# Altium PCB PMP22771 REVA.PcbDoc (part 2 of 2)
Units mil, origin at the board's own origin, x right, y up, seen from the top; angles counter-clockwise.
Board outline 3622.05 x 2204.72 mil, 4 copper layers (Top Layer, Signal Layer 1, Signal Layer 2, Bottom Layer), stack 35.634 mil thick; 91 components, 43 nets, 205 pads, 79 vias.
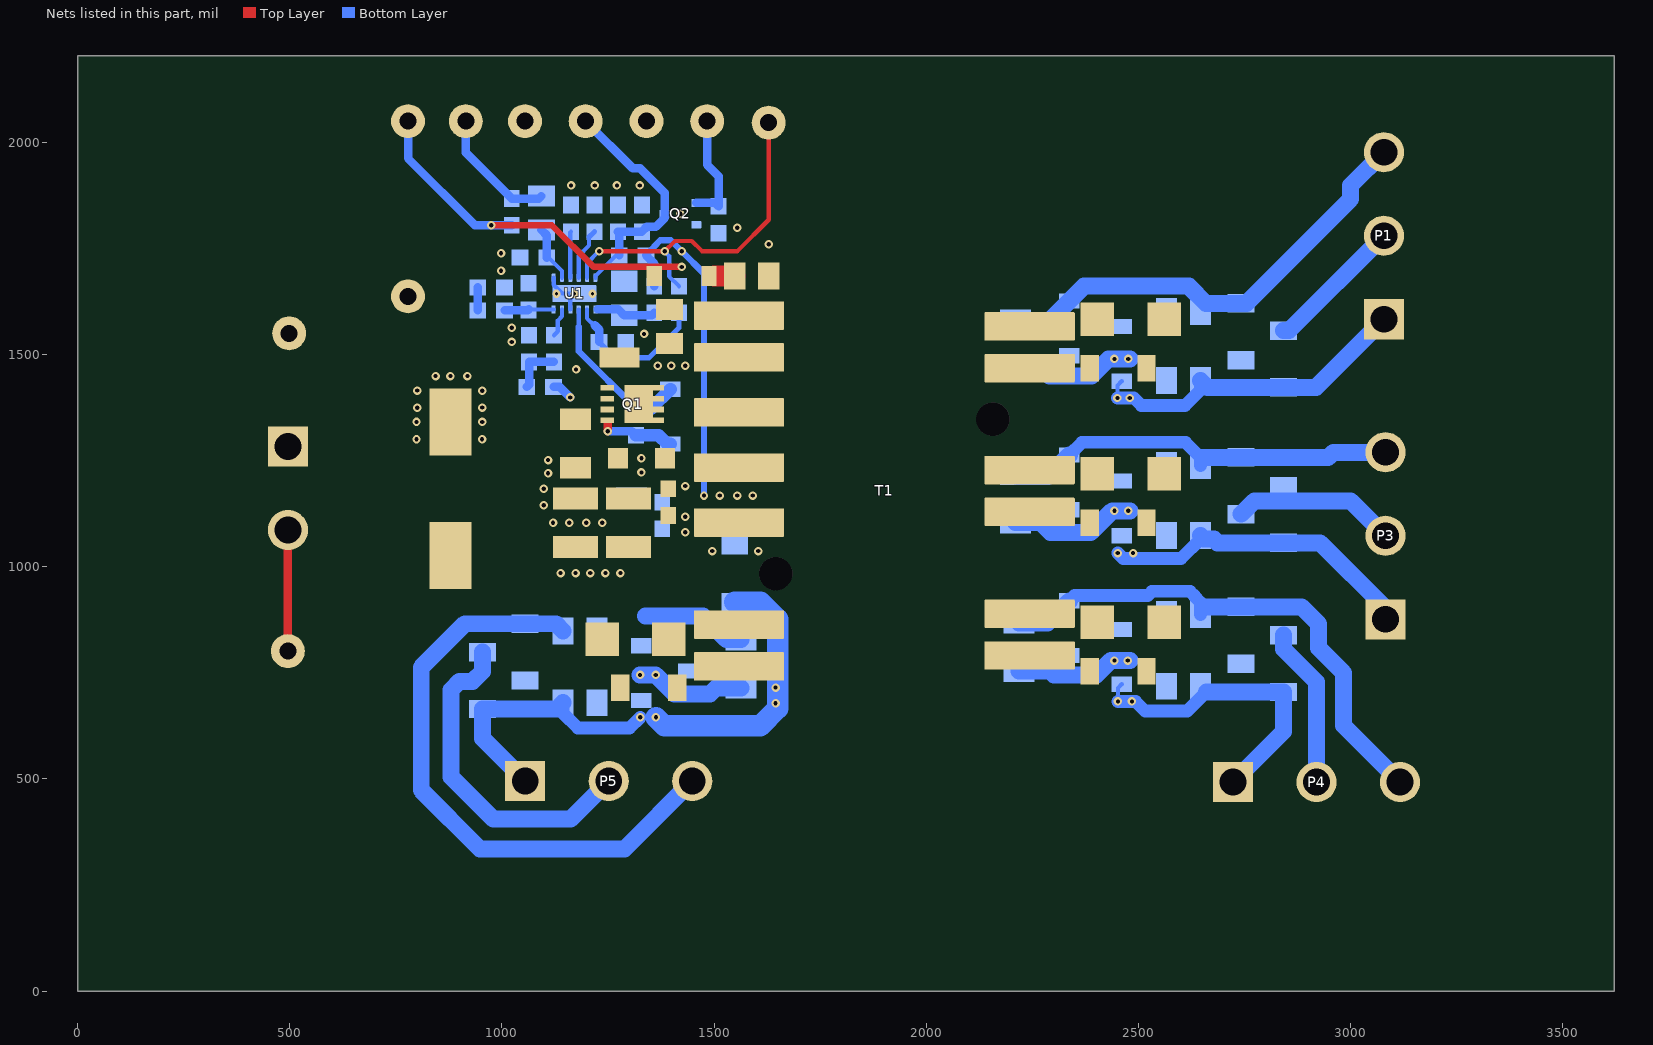
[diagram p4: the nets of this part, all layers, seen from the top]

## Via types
v1: diameter 20, hole 10, Top Layer to Bottom Layer, 76 vias
v2: diameter 19.68, hole 7.87, Top Layer to Bottom Layer, 3 vias

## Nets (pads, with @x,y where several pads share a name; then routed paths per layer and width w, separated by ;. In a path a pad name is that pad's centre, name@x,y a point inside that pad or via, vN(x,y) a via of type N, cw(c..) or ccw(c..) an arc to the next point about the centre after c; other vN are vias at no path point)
GND: C6.2 C7.2 C8.2 C9.2 C13.2 C16.2 C17.2 C21.2 C22.2 C23.2 C24.2 C25.2 C26.2 P2.1 Q2.2 R17.1 R21.1 R22.1 R26.1 R27.1 T1.2 TP2.1 TP8.1 TP9.1 TP10.1 U1.4 U1.7 U1.13@1171.25,1643.72 | length 115.9
  Bottom Layer w10: U1.7@1122.04,1681.12 1122.04,1664.47 1142.78,1643.72 v2(1171.25,1643.72) 1161.41,1633.88 U1.4@1161.41,1606.32
  other v1: 1495.85,1036.83 1604.33,1036.83 1120.69,1103.76 1158.82,1103.76 1198.82,1103.68 1236.81,1103.76 1098.82,1145.18 1098.82,1183.76 1432,1190.18 1108.82,1220.18 1108.82,1251.46 798.82,1300.18 953.3,1300.18 798.82,1341.24 953.82,1341.24 800.43,1374.7 953.82,1375.18 800.43,1415.18 953.82,1414.9 843.82,1449.26 878.82,1449.26 918.82,1449.26 1175,1465 1367.24,1473.72 1399.25,1473.72 1432.24,1473.72 1023.22,1529.88 1335.16,1548.6 1023.22,1562.95 998.22,1697.66 998.22,1738.72 1628.82,1760 1554.47,1798.72 1420.82,1831.67 1163.22,1898.72 1218.75,1898.72 1271.22,1898.72 1325.22,1898.72
  other v2: 1128.93,1643.72 1213.57,1643.72
GND2: C19.2 C20.2 C26.1 D14.2 P5.1 R20.1 T1.7 | length 1279.4
  Bottom Layer w30: R20.1@1144.29,679.57 1144.29,654.84 1179.13,620 1301.03,620 v1(1326.03,645)
  Bottom Layer w40: P5.1@1055,495 954.29,595.71 C20.2@954.29,664.86 1129.59,664.86 R20.1@1144.29,679.57
  Bottom Layer w50: v1(1362.96,645) 1382.96,625 1608.82,625 1650,666.18 1650,876.38 1609.62,916.75 C26.1@1548.82,916.75
  other v1: 1645,678.26 1645,715.19
NetC1_1: C1.1 D2.1 P1.3 R1.2 R2.2 | length 1084.9
  Bottom Layer w40: R1.2@2210.09,1580.81 2291.86,1580.81 D2.1@2337.24,1626.19 2372.15,1661.09 2618.91,1661.09 2659.35,1620.65 C1.1@2741.84,1620.65 2754.41,1620.65 2999.96,1866.2 2999.96,1898.11 P1.3@3078.7,1976.85
NetC1_2: C1.2 C3.1 D2.2 D3.1 P1.2 R2.1 R3.2 | length 329
  Bottom Layer w40: C3.1@2842.24,1556.51 2855.21,1556.51 P1.2@3078.7,1780
NetC2_1: C2.1 D1.1 R1.1 | length 293.5
  Bottom Layer w40: R1.1@2210.09,1466.63 2273.37,1466.63 2290,1450 2389.96,1450 2429.54,1489.58 v1(2443.5,1489.58) v1@2480.32,1489.58
  other v1: 2476,1489.58
NetC2_2: C2.2 C3.2 D3.2 P1.1 R3.1 T1.12 | length 789
  Bottom Layer w10: v1(2450.79,1397.64) 2450.79,1427.17 D3.2@2460.63,1437.01
  Bottom Layer w30: v1(2450.79,1397.64) v1(2480,1397.64) 2489.47,1397.64 2507.11,1380 2610,1380 2646.65,1416.65 R3.1@2646.65,1438.72
  Bottom Layer w40: R3.1@2646.65,1438.72 2662.71,1422.66 C3.2@2842.24,1422.66 2918.21,1422.66 P1.1@3078.7,1583.15
NetC4_1: C4.1 C6.1 C7.1 C8.1 C9.1 P2.2 R4.2 R8.2 R11.2 T1.4 T1.5 TP1.1 | length 1074.6
  Top Layer w20: TP1.1@495.71,801.08 495.71,1086.28 P2.2@495.94,1086.51
  Bottom Layer w15: R11.2@1339.71,1733.72 1358.62,1752.63 1358.62,1754.22 1373.49,1769.09 1375.08,1769.09 1375.71,1769.72 1397.86,1769.72 v1(1423.86,1743.72) 1476.38,1691.2 v1(1476.38,1167.73)
  Bottom Layer w20: R11.2@1339.71,1733.72 1359.25,1714.18 R8.2@1359.25,1661.24
  other v1: 1138.38,985.18 1173.82,985.18 1208.57,985.18 1243.97,985.18 1279.53,985.18 1432.24,1081.02 1432.24,1117.95 1513.31,1167.73 1554.47,1167.73 1591.4,1167.73
NetC4_2: C4.2 D4.1 R4.1
  other v1: 1328.82,1222.2 1328.82,1255.67
NetC5_1: C5.1 D6.1 P3.3 R5.2 R6.2 | length 941
  Bottom Layer w30: D6.1@2337.24,1263.19 2367.15,1293.09 2611.33,1293.09 2646.65,1257.78 R6.2@2646.65,1238.72
  Bottom Layer w40: R5.2@2210.39,1217.89 2215.63,1212.66 2286.71,1212.66 D6.1@2337.24,1263.19 ; R6.2@2652.03,1257.58 C5.1@2741.84,1257.58 2947.42,1257.58 2959.61,1269.77 P3.3@3082.52,1269.77
NetC5_2: C5.2 C11.1 D6.2 D7.1 P3.2 R6.1 R7.2 | length 387.6
  Bottom Layer w40: C5.2@2741.84,1123.72 2773.12,1155 3000.44,1155 P3.2@3082.52,1072.92
NetC10_1: C10.1 D5.1 R5.1 | length 300.4
  Bottom Layer w40: R5.1@2210.39,1103.72 2270.21,1103.72 2292.9,1081.02 2387.77,1081.02 2438.64,1131.89 v1(2443.5,1131.89) v1@2480.32,1131.89
  other v1: 2476,1131.89
NetC10_2: C10.2 C11.2 D7.2 P3.1 R7.1 T1.10 | length 761.5
  Bottom Layer w30: v1(2451.42,1032.35) 2464.43,1019.34 2600.72,1019.34 2646.24,1064.87 R7.1@2646.24,1073.72
  Bottom Layer w40: R7.1@2646.24,1073.72 2655.09,1064.87 2678.36,1064.87 2686.91,1056.32 C11.2@2842.24,1056.32 2928.68,1056.32 3082.52,902.48 P3.1@3082.52,876.07
  other v1: 2487.63,1032.35
NetC12_1: C12.1 D9.1 P4.3 R9.2 R10.2 | length 1240.4
  Bottom Layer w30: D9.1@2337.24,919.57 2349.77,932.1 2522.3,932.1 2532.18,941.98 2621.98,941.98 2632.24,931.71 2632.24,930.36 2646.65,915.95 R10.2@2646.65,887.6
  Bottom Layer w40: R9.2@2218.98,867.87 2285.54,867.87 D9.1@2337.24,919.57 ; R10.2@2651.71,905.65 C12.1@2741.84,905.65 2884.35,905.65 2925,865 2925,808.26 2983.15,750.11 2983.15,626.18 P4.3@3116.85,492.48
NetC12_2: C12.2 C15.1 D9.2 D10.1 P4.2 R10.1 R13.2 | length 378.4
  Bottom Layer w40: C15.1@2842.24,838.72 2842.24,806.3 2920,728.54 P4.2@2920,492.48
NetC13_1: C13.1 R8.1 U1.1 | length 146.8
  Bottom Layer w10: U1.1@1220.46,1606.32 1225.79,1606.36
  Bottom Layer w20: 1225.79,1606.36 1274.52,1606.32 C13.1@1288.22,1592.62 1353.62,1592.62 R8.1@1359.25,1598.25
NetC14_1: C14.1 D8.1 R9.1 | length 279.1
  Bottom Layer w40: R9.1@2218.98,753.69 2292.73,753.69 2301.68,744.74 2400.99,744.74 2434.97,778.72 v1(2443.5,778.72) v1@2480.32,778.72
  other v1: 2475,778.72
NetC14_2: C14.2 C15.2 D10.2 P4.1 R13.1 T1.8 | length 723.9
  Bottom Layer w10: v1(2451.97,682.48) 2451.97,714.28 D10.2@2460.63,722.93
  Bottom Layer w30: v1(2451.97,682.48) v1(2485,682.48) 2493.58,682.48 2516.06,660 2615.19,660 R13.1@2660.05,704.86
  Bottom Layer w40: R13.1@2660.05,704.86 C15.2@2842.24,704.86 2842.24,611.57 P4.1@2723.15,492.48
NetC16_1: C16.1 R28.2 U1.2 | length 357.4
  Bottom Layer w10: U1.2@1200.78,1606.32 1200.78,1585.41 1217.06,1569.13 1218.75,1569.13
  Bottom Layer w12: C16.1@1229.11,1529.88 1266.49,1492.5 1346.54,1492.5 1417.32,1563.28 R28.2@1417.32,1598.25
  Bottom Layer w20: 1218.75,1569.13 1229.46,1558.42 1229.11,1558.07 C16.1@1229.11,1529.88
NetC17_1: C17.1 R14.2 R15.1 | length 119.6
  Bottom Layer w20: R15.1@1058.77,1423.72 1064.12,1429.07 C17.1@1064.12,1482.65 R14.2@1122.57,1482.65
NetC18_1: C18.1 D13.1 P5.3 R16.2 R19.2 | length 1683.8
  Bottom Layer w40: R19.2@1144.16,848.72 1127.23,865.65 C18.1@1054.62,865.65 912.56,865.65 810,763.09 810,473.38 948.38,335 1288.7,335 P5.3@1448.7,495 ; 1338.23,883.37 D13.1@1439.24,883.37 1474.25,883.37 1528.88,828.74 R16.2@1563.7,828.74
NetC18_2: C18.2 C20.1 D13.2 D14.1 P5.2 R19.1 R20.2 | length 792.9
  Bottom Layer w40: C20.1@954.29,798.72 954.29,753.34 930.95,730 900.43,730 880,709.57 880,505 980,405 1161.85,405 P5.2@1251.85,495
NetC19_1: C19.1 D12.1 R16.1 | length 262.7
  Bottom Layer w40: v1(1325.57,745) v1(1362.5,745) 1407.34,700.16 1490,700.16 1504.41,714.57 R16.1@1563.7,714.57
NetC21_1: C21.1 Q2.3 R11.1 R21.2 TP4.1 U1.12 | length 577.1
  Bottom Layer w10: U1.12@1220.46,1681.12 1220.46,1685.05 1269.13,1733.72 R11.1@1276.72,1733.72
  Bottom Layer w20: TP4.1@1197.37,2050 1308.39,1938.98 1325.71,1938.98 1383.41,1881.28 Q2.3@1383.41,1831.67 1384,1831.09 1384,1822.06 1363.12,1801.18 1341.59,1801.18 C21.1@1330.13,1789.72 R21.2@1273.4,1789.72 1276.72,1786.4 R11.1@1276.72,1733.72
NetC22_1: C22.1 R23.2 U1.6 | length 116.6
  Bottom Layer w10: C22.1@1063.53,1606.32 U1.6@1122.04,1606.32
  Bottom Layer w20: R23.2@1006.37,1604.11 1061.33,1604.11 C22.1@1062.35,1605.14 C22.1@1063.53,1606.32
NetC23_1: C23.1 U1.9 | length 109.4
  Bottom Layer w10: U1.9@1161.41,1681.12 1161.41,1787.91 C23.1@1163.22,1789.72
NetC24_1: C24.1 R23.1 | length 54.2
  Bottom Layer w20: R23.1@943.38,1604.11 C24.1@943.38,1658.29
NetC25_1: C25.1 D15.1 R25.2 TP6.1 | length 886.9
  Top Layer w15: v1(975,1804.74) 1117.85,1804.74 1215.98,1706.62 v1(1423.86,1706.62)
  Bottom Layer w20: TP6.1@778.82,2050 778.82,1962.26 936.34,1804.74 v1(975,1804.74) R25.2@1023.22,1804.74
NetD1_2: D1.2 T1.13
NetD4_2: D4.2 Q1.5 Q1.6 Q1.7 Q1.8 Q1.9 T1.3 TP3.1
NetD5_2: D5.2 T1.11
NetD8_2: D8.2 T1.9
NetD11_1: D11.1 R12.1 U1.3 | length 389.4
  Bottom Layer w10: 1181.09,1565.94 U1.3@1181.09,1606.32
  Bottom Layer w15: 1181.09,1565.94 1181.09,1507.82 R12.1@1316.18,1372.73
  Bottom Layer w30: R12.1@1316.18,1372.73 1351.79,1372.73 D11.1@1397.24,1418.19
NetD11_2: D11.2 Q1.4 R12.2 | length 186.3
  Top Layer w10: Q1.4@1248.17,1344.9 1249.5,1343.56 1249.5,1336.92
  Top Layer w20: v1(1249.5,1319.29) 1249.5,1336.92
  Bottom Layer w20: v1(1249.5,1319.29) 1306.64,1319.29 R12.2@1316.18,1309.74
  Bottom Layer w30: R12.2@1316.18,1309.74 1369.5,1309.74 1389.99,1289.25 D11.2@1397.24,1289.25
NetD12_2: D12.2 T1.6
NetD15_2: D15.2 R18.1 | length 60.5
  Top Layer w30: D15.2@1488.28,1685.18 D15.2@1499.86,1685.18
  Top Layer w50: D15.2@1499.86,1685.18 R18.1@1548.82,1685.18
NetQ1_1: Q1.1 Q1.2 Q1.3 R15.2 R17.2 | length 49.5
  Bottom Layer w20: R15.2@1121.76,1423.72 1136.28,1423.72 v1(1161,1399)
NetQ2_1: Q2.1 R26.2 TP7.1 | length 268
  Bottom Layer w20: Q2.1@1458.22,1857.26 1502.79,1857.26 R26.2@1510.85,1849.21 1510.85,1920.17 1483.82,1947.2 TP7.1@1483.82,2050
NetR14_1: R14.1 U1.5 | length 68.6
  Bottom Layer w10: R14.1@1122.57,1545.65 1131.89,1554.97 1131.89,1580.32 1141.72,1590.15 U1.5@1141.72,1606.32
NetR18_2: R18.2 T1.1
NetR22_2: R22.2 U1.10 | length 124
  Bottom Layer w10: U1.10@1181.09,1681.12 1181.09,1732.89 1205.62,1757.42 R22.2@1205.62,1777.12
  Bottom Layer w12: R22.2@1205.62,1777.12 R22.2@1218.22,1789.72
NetR24_1: R24.1 R27.2 U1.8 | length 135.2
  Bottom Layer w10: R27.2@1105.9,1728.72 1110.23,1728.72 1141.72,1697.22 U1.8@1141.72,1681.12
  Bottom Layer w20: R24.1@1093.22,1793.72 1105.9,1781.04 R27.2@1105.9,1728.72
NetR24_2: R24.2 R25.1 TP5.1 | length 299.7
  Bottom Layer w20: TP5.1@915,2050 914.79,1976.16 R25.1@1023.22,1867.73 1087.23,1867.73 R24.2@1093.22,1873.72
NetR28_1: R28.1 TP11.1 U1.11 | length 849.4
  Top Layer w10: v1(1229.27,1743.71) v1(1384,1743.71) 1407.82,1767.53 1447.56,1767.53 1471.38,1743.71 1554.94,1743.71 1628.82,1817.59 TP11.1@1628.82,2046.46
  Bottom Layer w10: U1.11@1200.78,1681.12 1200.78,1715.22 v1(1229.27,1743.71) ; v1(1384,1743.71) 1384,1742.36 1394.24,1732.12 1394.24,1684.32 R28.1@1417.32,1661.24
pads on no net: T1. U1.13@1144.28,1643.72 U1.13@1198.22,1643.72

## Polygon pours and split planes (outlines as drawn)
GND on Top Layer "TOP_LAYER_GND_P092" (solid, remove dead copper, pour order 92): 1670,2204.72 1675,2199.72 1675,1030 0,1030 0,2204.72
GND on Top Layer "TOP_LAYER_GND_P090" (solid, remove dead copper, pour order 90): 1660,2210
GND2 on Top Layer "TOP_LAYER_GND2_P088" (solid, remove dead copper, pour order 88): 1662.82,797.24 1663.39,796.67 1663.39,679.57 1650,666.18 1420.28,666.18 1384.09,630 1325,630 1315,640 1315,663.26 1448.99,797.24 1465,797.24
NetC2_2 on Top Layer "TOP_LAYER_NETC2_2_P070" (solid, remove dead copper, pour order 70): 2145.67,1501.34 2407.54,1501.34 2416.81,1492.07 2416.81,1481.92 2497.99,1400.74 2497.99,1390.45 2490.82,1383.29 2366.71,1383.29 2312.99,1437.01 2147.86,1437.01 2145.67,1434.82
NetC14_2 on Top Layer "TOP_LAYER_NETC14_2_P068" (solid, remove dead copper, pour order 68): 2145.67,824.57 2349.05,824.57 2366.52,807.1 2397.7,807.1 2418.49,786.32 2418.49,765.08 2497.99,685.57 2497.99,676.15 2481.41,659.57 2397.16,659.57 2298.86,757.87 2145.67,757.87
NetC10_2 on Top Layer "TOP_LAYER_NETC10_2_P066" (solid, remove dead copper, pour order 66): 2145.67,1162.47 2402.51,1162.47 2419.8,1145.18 2419.8,1116.2 2497.99,1038.01 2497.99,1024.14 2487.63,1013.78 2396.49,1013.78 2312.99,1097.28 2145.67,1097.28
NetC19_1 on Top Layer "TOP_LAYER_NETC19_1_P048" (solid, remove dead copper, pour order 48): 1200.79,868.72 1329.05,868.72 1338.55,859.22 1338.55,805.17 1372.53,771.19 1372.53,739.86 1312.76,680.1 1249.33,680.1 1200.79,728.64
NetD12_2 on Top Layer "TOP_LAYER_NETD12_2_P042" (solid, remove dead copper, pour order 42): 1663.39,898.46 1408.04,898.46 1378.29,868.72 1353.84,868.72 1353.84,790.99 1419.5,790.77 1460.03,831.3 1662.82,831.3
NetC14_1 on Top Layer "TOP_LAYER_NETC14_1_P040" (solid, remove dead copper, pour order 40): 2598.43,907.62 2470.26,907.62 2457.24,894.6 2457.24,825.6 2433.33,801.68 2433.33,772.78 2438.39,767.72 2486.21,719.9 2544.92,719.9 2598.43,773.4
NetD8_2 on Top Layer "TOP_LAYER_NETD8_2_P036" (solid, remove dead copper, pour order 36): 2440.2,831.21 2440.2,914.03 2429.6,924.62 2153.54,924.62 2145.67,916.75 2145.67,856.3 2342.48,856.3 2366.71,832.07
NetC2_1 on Top Layer "TOP_LAYER_NETC2_1_P032" (solid, remove dead copper, pour order 32): 2598.43,1621.72 2472.6,1621.72 2457.24,1606.36 2457.24,1531.87 2433.08,1507.71 2433.08,1484.24 2480.32,1437.01 2537.97,1437.01 2598.43,1497.46
NetD1_2 on Top Layer "TOP_LAYER_NETD1_2_P028" (solid, remove dead copper, pour order 28): 2145.67,1598.25 2336.39,1598.25 2362.16,1624.02 2440.94,1624.02 2440.94,1543.4 2432.97,1535.43 2145.67,1535.43
NetC10_1 on Top Layer "TOP_LAYER_NETC10_1_P026" (solid, remove dead copper, pour order 26): 2598.43,1255.67 2473.65,1255.67 2458.14,1240.16 2458.14,1168.63 2451.97,1162.47 2433.78,1144.27 2433.78,1124.9 2456.31,1102.36 2488.86,1069.82 2536.36,1069.82 2598.43,1131.89
NetD5_2 on Top Layer "TOP_LAYER_NETD5_2_P022" (solid, remove dead copper, pour order 22): 2145.67,1261.14 2147.27,1259.55 2440.94,1259.55 2440.94,1180.49 2361.25,1180.49 2345.24,1196.49 2145.67,1196.49
NetC25_1 on Top Layer "TOP_LAYER_NETC25_1_P020" (solid, remove dead copper, pour order 20): 1427.17,1583.48 1427.17,1643.08 1439.24,1655.15 1439.24,1706.44 1430.66,1715.02 1354.93,1715.02 1342.67,1702.76 1342.67,1602.8 1364.66,1580.81 1427.17,1580.81
NetR18_2 on Top Layer "TOP_LAYER_NETR18_2_P016" (solid, remove dead copper, pour order 16): 1663.39,1561.72 1662.82,1562.29 1662.82,1712.6 1656.97,1718.44 1604.33,1718.44 1604.33,1656.63 1574.8,1627.1 1574.8,1624.02 1525.04,1624.02 1510.85,1609.82 1510.85,1576.92 1524.82,1562.95
NetQ1_1 on Top Layer "TOP_LAYER_NETQ1_1_P008" (solid, remove dead copper, pour order 8): 1269.68,1363.6 1269.68,1423.99 1257.06,1436.61 1166.69,1436.61 1138.38,1408.3 1138.38,1318.9 1209.94,1318.9 1210.63,1319.59 1209.23,1320.99 1209.23,1347.3 1225.53,1363.6
NetC4_2 on Top Layer "TOP_LAYER_NETC4_2_P004" (solid, remove dead copper, pour order 4): 1248.22,1279.86 1248.22,1221.85 1249,1221.85 1260.22,1210.63 1334.05,1210.63 1339.71,1216.3 1339.71,1261.14 1329.31,1271.55 1307.88,1271.55 1299.21,1280.22
NetD4_2 on Top Layer "TOP_LAYER_NETD4_2_P006" (solid, remove dead copper, pour order 6): 1663.39,1300.18 1663.39,1427.17 1427.17,1427.17 1407.48,1446.85 1356.74,1446.85 1329.87,1473.72 1330.13,1511.81 1326.19,1515.75 1229.27,1515.75 1229.27,1446.85 1269.69,1446.85 1279.53,1437.01 1279.13,1436.61 1279.13,1312.79 1361.61,1230.32 1407.82,1230.32 1407.82,1254.62 1453.37,1300.18
NetC4_1 on Top Layer "TOP_LAYER_NETC4_1_P002" (solid, remove dead copper, pour order 2): 442.91,1141.73 423.23,1122.05 423.23,968.4 442.91,948.72 1010.2,948.72 1035.89,974.41 1287.78,974.41 1328.74,1015.37 1348.59,1015.37 1403.04,1069.82 1663.39,1069.82 1663.39,1267.26 1453.31,1267.26 1453.7,1266.87 1453.7,1185.15 1389.04,1120.49 1322.4,1120.49 1281.91,1080 1110.86,1080 1049.13,1141.73
GND on Bottom Layer "BOTTOM_LAYER_GND_P094" (solid, remove dead copper, pour order 94): 1675,2204.72 1675,1030 0,1030 0,2204.72
NetC18_1 on Bottom Layer "BOTTOM_LAYER_NETC18_1_P086" (solid, remove dead copper, pour order 86): 1150.45,860 1181.81,891.36 1302.08,891.36 1327.72,865.72 1358.67,865.72 1358.67,883.39 1322.07,920 1160.29,920 1120,879.71 1120,860
NetC18_2 on Bottom Layer "BOTTOM_LAYER_NETC18_2_P082" (solid, remove dead copper, pour order 82): 1415,738.9 1465,738.9 1465,839.11 1424.11,880 1190.86,880 1131.03,820.18 925,820.18 925,710 1141.02,710 1201.02,650 1293.41,650 1383.41,740
GND2 on Bottom Layer "BOTTOM_LAYER_GND2_P080" (solid, remove dead copper, pour order 80): 1305,700 1305,629.35 1314.35,620 1359.22,620 1375,635.78 1375,662.89 1337.89,700
NetC1_2 on Bottom Layer "BOTTOM_LAYER_NETC1_2_P078" (solid, remove dead copper, pour order 78): 2312.99,1480 2312.99,1544.22 2394.96,1626.19 2598.81,1626.19 2650,1575 2874.02,1575 2874.02,1466.63 2649.98,1466.63 2590,1406.65 2539.24,1406.65 2510.89,1435 2510.89,1497.25 2508.14,1500 2430,1500 2410,1480
NetC2_2 on Bottom Layer "BOTTOM_LAYER_NETC2_2_P076" (solid, remove dead copper, pour order 76): 2460.63,1437.01 2453.62,1430 2441.81,1430 2429.5,1417.69 2429.5,1386.18 2435.69,1380 2526.67,1380 2470.47,1436.2 2470.47,1437.01
NetC14_2 on Bottom Layer "BOTTOM_LAYER_NETC14_2_P074" (solid, remove dead copper, pour order 74): 2426.77,679.13 2426.77,700.16 2443.5,716.89 2478.74,716.89 2529.91,665.72 2470.47,665.39 2440.51,665.39
NetC12_2 on Bottom Layer "BOTTOM_LAYER_NETC12_2_P072" (solid, remove dead copper, pour order 72): 2312.99,771.79 2312.99,836.75 2381.89,905.65 2598.29,905.65 2647.64,856.3 2874.02,856.3 2874.02,748.03 2637.8,748.03 2588.58,698.82 2545.14,698.82 2512.28,731.68 2512.28,765.28 2505.77,771.79
NetC10_2 on Bottom Layer "BOTTOM_LAYER_NETC10_2_P062" (solid, remove dead copper, pour order 62): 2483.29,1091.4 2483.29,1057.39 2483.82,1057.39 2516.35,1024.86 2504.16,1012.66 2436.75,1012.66 2426.77,1022.64 2426.77,1050.83 2451.42,1075.49 2451.42,1091.4
NetC5_2 on Bottom Layer "BOTTOM_LAYER_NETC5_2_P060" (solid, remove dead copper, pour order 60): 2312.99,1113.56 2399.25,1113.56 2418.7,1133.01 2512.28,1133.01 2512.28,1070.4 2539.37,1043.31 2585.93,1043.31 2644.89,1102.26 2874.02,1102.26 2874.02,1212.66 2647.03,1212.66 2595.77,1263.91 2393.77,1263.91 2312.99,1183.13
NetC4_1 on Bottom Layer "BOTTOM_LAYER_NETC4_1_P014" (solid, remove dead copper, pour order 14): 1135.38,1053.56 1127.56,1045.74 1127.56,981.53 1134.67,974.41 1378.72,974.41 1506.67,1102.36 1578.76,1102.36 1609.96,1133.56 1609.96,1174.7 1593.72,1190.94 1473.6,1190.94 1413.38,1130.73 1413.38,1123.71 1406.26,1116.6 1285.86,1116.6 1222.82,1053.56
NetC4_2 on Bottom Layer "BOTTOM_LAYER_NETC4_2_P012" (solid, remove dead copper, pour order 12): 1399.25,1131.89 1399.25,1201.61 1333.99,1266.87 1314.35,1266.87 1269.68,1222.2 1269.68,1131.89 1353.51,1131.89
GND on Signal Layer 1 "SIGNAL_LAYER_1_GND_P102" (solid, remove dead copper, pour order 102): 0,2204.72 1674,2204.72 1674,1456.47 1667,1449.47 1423.69,1449.47 1411.01,1462.14 1363.07,1462.14 1344.83,1480.39 1344.83,1515.72 1327.55,1533 1226.54,1533 1213.98,1520.44 1213.98,1437.02 1262,1389 1262,1249.75 1316.16,1195.59 1389.67,1195.59 1437.34,1243.25 1437.34,1250.74 1455.6,1269 1675,1269 1675,1030 0,1030
GND on Signal Layer 1 "SIGNAL_LAYER_1_GND_P098" (solid, remove dead copper, pour order 98): 235,2270
GND on Signal Layer 2 "SIGNAL_LAYER_2_GND_P100" (solid, remove dead copper, pour order 100): 0,2204.72 1675,2204.72 1675,1032.36 1672.64,1030 0,1030

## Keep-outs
Keep-Out Layer:
  text ".Layer_Name" at 577,-858.49 h60

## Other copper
Top Layer:
  text ".Layer_Name" at 577,-858.49 h60
Bottom Layer:
  text ".Layer_Name" at 577,-858.49 h60

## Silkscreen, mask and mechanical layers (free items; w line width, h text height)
Top Overlay:
  text "'.PRJ_Number'.PCB_Rev" at 2060,2010 h108.27
  text "+18V2" at 3570,1910.51 h72.83 r90
  text "RTN2" at 3570,1700.01 h72.83 r90
  text "-5.1V2" at 3570,1465 h72.83 r90
  text "GND" at 30,1390 h72.83 r270
  text "+18V3" at 3575,1200 h72.83 r90
  text "VIN" at 30,1089.27 h72.83 r270
  text "RTN3" at 3575,990.25 h72.83 r90
  text "-5.1V3" at 3575,755 h72.83 r90
  text "-5.1V1" at 915,30 h72.83
  text "+18V1" at 1405,30 h72.83
  text "-5.1V4" at 2580,30 h72.83
  text "+18V4" at 3070,30 h72.83
  text "RTN1" at 1180,25 h72.83
  text "RTN4" at 2845,25 h72.83
  text ".Layer_Name" at 577,-858.49 h60
Bottom Overlay:
  lines w8: 878.82,1543.15 908.69,1570.03 908.69,1570.41 ; 1034.85,1349.86 1061.33,1387.85 ; 1377.33,1725 1437.59,1725
  text ".Layer_Name" at 577,-858.49 h60
Top Paste:
  text ".Layer_Name" at 577,-858.49 h60
Bottom Paste:
  text ".Layer_Name" at 577,-858.49 h60
Top Solder:
  text ".Layer_Name" at 577,-858.49 h60
  text ".Layer_Name" at 577,-858.49 h60
Bottom Solder:
  text ".Layer_Name" at 577,-858.49 h60
Drill Guide:
  text ".Layer_Name" at 577,-858.49 h60
M1 Board Outline:
  lines w8: 0,0 0,2204.72 3622.05,2204.72 3622.05,0 0,0
  lines w10: 0,0 0,2204.72 3622.05,2204.72 3622.05,0 0,0
  text ".Layer_Name" at 577,-858.49 h60
M2 Board Dimensions:
  rectangle: 0,-275 125,-150
  rectangle: 125,-400 500,-275
  lines w7: 0,-275 1000,-275 ; 125,-400 125,-150 ; 250,-400 250,-150 ; 500,-400 500,-150 ; 750,-400 750,-150 ; 0,-400 1000,-400 1000,-150 0,-150 0,-400
  text ".Layer_Name" at 577,-858.49 h60
M3 3D STEP Top:
  text ".Layer_Name" at 577,-858.49 h60
M4 3D STEP Bottom:
  text ".Layer_Name" at 577,-858.49 h60
M5 Assembly Top:
  lines w8: 102.24,948.72 102.24,1421.16 ; 104.68,951.16 573.52,951.16 573.52,1421.16 102.24,1421.16 ; 102.24,1421.16 102.24,1421.16 ; 102.24,1421.16 102.24,1421.16 ; 102.24,1421.16 102.24,1421.16 ; 917.2,105 917.2,570 1586.5,570 1586.5,105 917.2,105 ; 2585.35,100 2585.35,565 3254.65,565 3254.65,100.35 3255,100 2585.35,100 ; 3000,1445.35 3000,2114.65 3474.65,2114.65 3474.65,1445.35 3000,1445.35 ; 3003.78,740 3003.78,1405 3472.44,1405 3475,741.22 3005,741.22 3003.78,740
  lines w10: -292,-930.17 6308,-930.17 ; -292,-726.83 6310,-726.83 ; -292,-523.5 -292,-1133.5 3713,-1133.5 6310,-1133.5 6310,-523.5 -291.5,-523.5 -291.5,-1133.5 1284,-1133.5 ; 2173,-1133.5 2173,-523.5 ; 3440,-726.83 3440,-523.5 ; 4280,-726.83 4280,-523.5 ; 4902,-1140 4902,-937.17
  text "PMP22771A" at 2060,2010 h110
  text "P1" at 3225,1760 h72.83
  text "P2" at 300,1165 h72.83
  text "P3" at 3220,1052.92 h72.83
  text "P4" at 2885,300 h72.83
  text "P5" at 1215,290 h72.83
  text "COMPONENTS MARKED 'DNP' SHOULD NOT BE POPULATED." at 1153.5,-318.5 h60
  text "ASSEMBLY VARIANT:" at 1153,-434 h60
  text ".VariantName" at 2189,-434 h60
  text "PCB VIEWED FROM TOP SIDE" at -228.5,-655.67 h60
  text "BOARD #:" at 2248,-655.67 h60
  text ".PRJ_Number" at 2793.5,-655.67 h60
  text "REV:" at 3638,-655.67 h60
  text ".PCB_Rev" at 3929.5,-655.67 h60
  text "SVN REV:" at 4476,-655.67 h60
  text ".VersionControl_RevNumber" at 4982,-655.67 h60
  text "TID #:" at 2248,-859 h60
  text ".TID" at 2793.5,-859 h60
  text "PLOT NAME =" at -228.5,-1064.34 h60
  text ".plot_File_Name" at 577,-1064.34 h60
  text "GENERATED    :" at 2250,-1064.34 h60
  text ".Print_Date" at 3119.5,-1064.34 h60
  text ".Print_Time" at 3848.5,-1064.34 h60
  text "TEXAS INSTRUMENTS" at 5113,-1064.34 h60
M6 Assembly Bottom:
  lines w10: -292.5,-727.33 6309.5,-727.33 ; -290.5,-930.67 6309.5,-930.67 ; 1115.5,-1140.5 1115.5,-937.67 ; 1737.5,-727.33 1737.5,-524 ; 2577.5,-727.33 2577.5,-524 ; 3844.5,-1134 3844.5,-524 ; 4733.5,-1134 6309,-1134 6309,-524 -292.5,-524 -292.5,-1134 2304.5,-1134 6309.5,-1134 6309.5,-524
  text "COMPONENTS MARKED 'DNP' SHOULD NOT BE POPULATED." at 6102,-318 h60
  text ".VariantName" at 5058,-434 h60
  text "ASSEMBLY VARIANT:" at 6097,-434 h60
  text ".VersionControl_RevNumber" at 1035.5,-656.17 h60
  text "SVN REV:" at 1541.5,-656.17 h60
  text ".PCB_Rev" at 2088,-656.17 h60
  text "REV:" at 2379.5,-656.17 h60
  text ".PRJ_Number" at 3224,-656.17 h60
  text "BOARD #:" at 3769.5,-656.17 h60
  text "PCB VIEWED FROM BOTTOM SIDE" at 6246,-656.17 h60
  text ".TID" at 3224,-859.5 h60
  text "TID #:" at 3769.5,-859.5 h60
  text "TEXAS INSTRUMENTS" at 904.5,-1064.84 h60
  text ".Print_Time" at 2169,-1064.84 h60
  text ".Print_Date" at 2898,-1064.84 h60
  text "GENERATED    :" at 3767.5,-1064.84 h60
  text ".plot_File_Name" at 5440.5,-1064.84 h60
  text "PLOT NAME =" at 6246,-1064.84 h60
M9 Title Sheet:
  drawing of 57 lines, arcs and shapes, not listed
  text "1" at 739.84,8036.5 h70
  text "2" at 3235.5,8036.5 h70
  text "3" at 5724.84,8036.5 h70
  text "4" at 8231.51,8036.5 h70
  text "5" at 10730.5,8036.5 h70
  text "6" at 13235.5,8036.5 h70
  text "A" at -416.5,6893.5 h70
  text "A" at 14383.5,6893.5 h70
  text "B" at -416.5,4513.5 h70
  text "B" at 14383.5,4513.5 h70
  text "C" at -416.5,2138.5 h70
  text "C" at 14383.5,2138.5 h70
  text "PROJECT TITLE:" at 11343.5,277.5 h45
  text ".PRJ_Title" at 11393.5,144.17 h70
  text "DESIGNED FOR:" at 11343.5,-23.5 h45
  text ".PRJ_Customer" at 11393.5,-163.5 h70
  text "D" at -416.5,-231.5 h70
  text "D" at 14383.5,-231.5 h70
  text "FILE NAME:" at 11343.5,-323.5 h45
  text ".PCB_File_Name_No_Path" at 11393.5,-443.5 h70
  text "Texas Instruments (TI) and/or its licensors do not warrant the accuracy or completeness of this specification" at 6374,-605.34 h45
  text "ENGINEER:" at 11343.5,-613.5 h45
  text "LAYOUT BY:" at 12848.5,-613.5 h45
  text "or any information contained therein. TI and/or its licensors do not warrant that this design will meet" at 6329.01,-718 h45
  text ".PRJ_Engineer" at 11393.5,-768.49 h70
  text ".PCB_Layout" at 12899,-768.49 h70
  text "the specifications, will be suitable for your application or fit for any particular purpose, or will operate in" at 6329.01,-830.67 h45
  text ".Layer_Name" at 577,-858.49 h60
  text "ALTIUM DESIGNER VERSION:" at 12848.5,-923.5 h45
  text "an implementation. TI and/or its licensors do not warrant that the design is production worthy. You should" at 6329.01,-943.33 h45
  text "completely validate and test your design implementation to confirm the system functionality for your application." at 6374,-1056 h45
  text ".print_Scale" at 11393.5,-1056.83 h70
  text ".Application_BuildNumber" at 12899,-1056.83 h70
  text "1" at 739.84,-1263.5 h70
  text "2" at 3235.5,-1263.5 h70
  text "3" at 5724.84,-1263.5 h70
  text "4" at 8231.51,-1263.5 h70
  text "5" at 10730.5,-1263.5 h70
  text "6" at 13235.5,-1263.5 h70
M10 Fab Notes:
  drawing of 189 lines, arcs and shapes, not listed
  text "DESIGN INFORMATION" at 12382.02,6356.17 h60
  text "MIN. TRACK WIDTH:" at 11737.46,6224.05 h60
  text "8" at 12833.7,6224.05 h60
  text "MIL" at 12988.46,6224.05 h60
  text "MIN. CLEARANCE:" at 11737.46,6099.92 h60
  text "0.2" at 12773.7,6099.93 h60
  text "mm" at 12988.46,6099.92 h60
  text "MIN. VIA PAD SIZE:" at 11737.46,5975.8 h60
  text "24" at 12803.71,5975.8 h60
  text "MIL" at 12988.46,5975.8 h60
  text "0.05mm (2MIL)" at 12432.46,5845.9 h60
  text "MINIMUM ANNULAR RING" at 11408.23,5837.67 h60
  text "EXTERNAL" at 13140.46,5837.67 h60
  text "PER" at 11608.23,5727.55 h60
  text "IPC-D-275 CLASS 2 LEVEL C" at 11828.23,5727.54 h60
  text "MIL, HOLES" at 13316.46,5627.07 h60
  text "+/-" at 12924,5618.48 h60
  text "+/-" at 13778,5618.48 h60
  text "REGISTRATION TOLERANCES:" at 11408.23,5617.42 h60
  text "METAL" at 12608,5617.42 h60
  text "5" at 13184.2,5617.42 h60
  text "3" at 14017.2,5617.42 h60
  text "MIL" at 14133.46,5617.42 h60
  text "HOLE SIZE TOLERANCE (UNLESS OTHERWISE SPECIFIED):" at 11408.23,5519.1 h60
  text "+/-" at 13778,5516.23 h60
  text "3" at 14017.2,5515.17 h60
  text "MIL" at 14133.46,5515.17 h60
  text "MATERIAL:" at 11333.46,5377.52 h60
  text "FR-4 High Tg" at 12319.9,5249 h60
  text "X" at 12175.46,5241.01 h60
  text "FR-408" at 11754.46,5236.49 h60
  text "OTHER" at 13242.46,5236.49 h60
  text "62 MIL (1.6mm) +/-10%" at 12074.56,5093.46 h60
  text "X" at 11954.46,5091.01 h60
  text "THICKNESS:" at 11408.23,5085.24 h60
  text "OTHER" at 13359.46,5085.24 h60
  text "TOLERANCE:" at 11408.23,4946.92 h60
  text "X" at 12256.46,4946.92 h60
  text "ANSI IPC-6012 TYPE 3 CLASS 2" at 12434.48,4946.92 h60
  text "OTHER +/-" at 12434.46,4802.73 h60
  text "BOW & TWIST:" at 11408.23,4657.54 h60
  text "X" at 12256.46,4657.54 h60
  text "ANSI IPC-6012 TYPE 3 CLASS 2" at 12434.48,4657.54 h60
  text "OTHER +/-" at 12434.46,4510.85 h60
  text "DRILLING:" at 11333.46,4380.23 h60
  text "NC_DRILL FILES" at 13094.46,4275.04 h60
  text "REFERENCE:" at 11408.23,4271.1 h60
  text "X" at 12065.46,4271.01 h60
  text "AS SHOWN" at 12243.46,4271.1 h60
  text "X" at 12966.46,4271.1 h60
  text "OTHER" at 13392.46,4128.85 h60
  text "PTH COPPER THICKNESS:" at 11407.91,4125.32 h60
  text "X" at 12547.14,4125.32 h60
  text "20-30 um" at 12675.14,4125.32 h60
  text "BOARD FINISH:" at 11333.46,3977.73 h60
  text "SILKSCREEN:" at 11488.68,3867.6 h60
  text "X" at 12446.46,3867.6 h60
  text "TOP" at 12563.46,3867.6 h60
  text "X" at 12956.46,3867.6 h60
  text "BOTTOM" at 13074.46,3867.6 h60
  text "SILKSCREEN COLOR:" at 11488.68,3712.41 h60
  text "X" at 12445.46,3712.41 h60
  text "WHITE" at 12563.46,3712.41 h60
  text "OTHER" at 13074.46,3712.41 h60
  text "X" at 12576.46,3568.96 h60
  text "GREEN" at 12694.46,3568.96 h60
  text "OTHER" at 13312.46,3568.96 h60
  text "SOLDER RESIST COLOR:" at 11488.68,3562.1 h60
  text "X" at 12576.46,3414.71 h60
  text "MATTE" at 12694.46,3414.71 h60
  text "SEMI-GLOSS" at 13312,3414.07 h60
  text "IMMERSION GOLD (ENIG)" at 12394.46,3241.94 h60
  text "ENEPIG" at 13732,3234.72 h60
  text "SURFACE FINISH:" at 11333.46,3233.72 h60
  text "X" at 12216.46,3233.72 h60
  text "IMM. TIN/SILVER OR EQUIV" at 11663,3096.4 h60
  text "OTHER" at 13094.46,3092.47 h60
  text "ARRAY/PANEL:" at 11333.46,2937.09 h60
  text "CUT AND TRIM PER M1 BOARD OUTLINE" at 12394.46,2928.87 h60
  text "N.C. ROUTE" at 12394.46,2792.9 h60
  text "X" at 13082.46,2792.9 h60
  text "V. SCORE" at 13260.46,2792.9 h60
  text "CERTIFICATION:" at 11333.46,2663.77 h60
  text "MATERIALS AND WORKMANSHIP FOR ALL PCBS" at 12058.46,2663.77 h60
  text "TO MEET OR EXCEED THE REQUIREMENTS OF:" at 12058.46,2569.71 h60
  text "X" at 11695.97,2441.08 h60
  text "ANSI IPC-A-600F CLASS ->" at 11823.96,2441.08 h60
  text "X" at 13471.97,2441.08 h60
  text "2" at 13581.96,2441.08 h60
  text "1" at 13266.96,2439.58 h60
  text "3" at 13935.96,2439.58 h60
  text "X" at 12507.97,2293.39 h60
  text "RoHS" at 12635.96,2293.39 h60
  text "OTHER" at 13280.36,2293.39 h60
  text "PER ORDER" at 13677.42,2293.39 h60
  text "ALL BOARDS MUST MEET OR EXCEED UL94-V0 REQUIREMENTS." at 11361,2139.57 h60
  text "PCB MUST BEAR THE UL94V-0 UL REGISTERED MATERIAL ID NUMBER" at 11361,2023.5 h60
  text "ADDITIONAL REQUIREMENTS:" at 11333.46,1854.08 h60
  text "MICROSECTION:" at 11408.23,1746.95 h60
  text "YES" at 12313.96,1746.95 h60
  text "REQUIRED" at 13175.46,1602.62 h60
  text "BARE BOARD ELEC. TEST:" at 11408.23,1599.76 h60
  text "NONE" at 12713.96,1599.76 h60
  text "X" at 13057.46,1599.76 h60
  text "PER ORDER" at 13767.46,1599.76 h60
  text "XX MIL VIAS REQUIRE NON-CONDUCTIVE FILL AND PLANARIZE" at 11576.38,1394.82 h59
  text "XX MIL VIAS REQUIRE CONDUCTIVE FILL AND PLANARIZE" at 11584.38,1290.84 h60
  text "OUTER XX MIL TRACES REQUIRE 50 OHM SINGLE-ENDED IMPEDANCE" at 11583.39,1127.46 h58
  text "LAYER 2 & 3 (INNER LAYERS) XX MIL WIDE, XX MIL SPACE / TRACES REQUIRE 100 OHM DIFFERENTIAL IMPEDANCE" at 11575.39,891.74 h60
  text ".Layer_Name" at 577,-858.49 h60
M11 Gerber Information:
  lines w10: -292,-930.17 6308,-930.17 ; -292,-726.83 6310,-726.83 ; -292,-523.5 -292,-1133.5 3713,-1133.5 6310,-1133.5 6310,-523.5 -291.5,-523.5 -291.5,-1133.5 1284,-1133.5 ; 2173,-1133.5 2173,-523.5 ; 3440,-726.83 3440,-523.5 ; 4280,-726.83 4280,-523.5 ; 4902,-1140 4902,-937.17
  text "ALL ARTWORK VIEWED FROM TOP SIDE" at -228.5,-655.67 h60
  text "BOARD #:" at 2248,-655.67 h60
  text ".PRJ_Number" at 2793.5,-655.67 h60
  text "REV:" at 3638,-655.67 h60
  text ".PCB_Rev" at 3929.5,-655.67 h60
  text "SVN REV:" at 4476,-655.67 h60
  text ".VersionControl_RevNumber" at 4982,-655.67 h60
  text "LAYER NAME =" at -228.5,-858.49 h60
  text "TID #:" at 2248,-859 h60
  text ".TID" at 2793.5,-859 h60
  text "PLOT NAME =" at -228.5,-1064.34 h60
  text ".plot_File_Name" at 577,-1064.34 h60
  text "GENERATED    :" at 2250,-1064.34 h60
  text ".Print_Date" at 3119.5,-1064.34 h60
  text ".Print_Time" at 3848.5,-1064.34 h60
  text "TEXAS INSTRUMENTS" at 5113,-1064.34 h60
M12 Stackup:
  drawing of 295 lines, arcs and shapes, not listed
  text "Layer" at 9774.58,7846 h60
  text "Name" at 10184.49,7846 h60
  text "Material" at 11124.23,7846 h60
  text "Thickness" at 11984,7846 h60
  text "Constant" at 12633.84,7846 h60
  text "Board Layer Stack" at 13203.7,7846 h60
  text "1" at 9774.58,7726 h60
  text "Top Overlay" at 10184.49,7726 h60
  text "2" at 9774.58,7606 h60
  text "Top Solder" at 10184.49,7606 h60
  text "Solder Resist" at 11124.23,7606 h60
  text "0.40mil" at 11984,7606 h60
  text "3.5" at 12633.84,7606 h60
  text "3" at 9774.58,7486 h60
  text "Top Layer" at 10184.49,7486 h60
  text "Copper" at 11124.23,7486 h60
  text "1.40mil" at 11984,7486 h60
  text "4" at 9774.58,7366 h60
  text "Dielectric1" at 10184.49,7366 h60
  text "FR-4" at 11124.23,7366 h60
  text "10.00mil" at 11984,7366 h60
  text "4.2" at 12633.84,7366 h60
  text "5" at 9774.58,7246 h60
  text "Signal Layer 1" at 10184.49,7246 h60
  text "Copper" at 11124.23,7246 h60
  text "1.42mil" at 11984,7246 h60
  text "6" at 9774.58,7126 h60
  text "Dielectric 2" at 10184.49,7126 h60
  text "10.00mil" at 11984,7126 h60
  text "4.2" at 12633.84,7126 h60
  text "7" at 9774.58,7006 h60
  text "Signal Layer 2" at 10184.49,7006 h60
  text "Copper" at 11124.23,7006 h60
  text "1.42mil" at 11984,7006 h60
  text "8" at 9774.58,6886 h60
  text "Dielectric 3" at 10184.49,6886 h60
  text "FR-4" at 11124.23,6886 h60
  text "10.00mil" at 11984,6886 h60
  text "4.2" at 12633.84,6886 h60
  text "9" at 9774.58,6766 h60
  text "Bottom Layer" at 10184.49,6766 h60
  text "Copper" at 11124.23,6766 h60
  text "1.40mil" at 11984,6766 h60
  text "10" at 9774.58,6646 h60
  text "Bottom Solder" at 10184.49,6646 h60
  text "Solder Resist" at 11124.23,6646 h60
  text "0.40mil" at 11984,6646 h60
  text "3.5" at 12633.84,6646 h60
  text "11" at 9774.58,6526 h60
  text "Bottom Overlay" at 10184.49,6526 h60
  text ".Layer_Name" at 577,-858.49 h60
M13 Component Bodies Top:
  text ".Layer_Name" at 577,-858.49 h60
M14 Component Bodies Bottom:
  text ".Layer_Name" at 577,-858.49 h60
M15 Courtyards Top:
  text ".Layer_Name" at 577,-858.49 h60
M16 Courtyards Bottom:
  text ".Layer_Name" at 577,-858.49 h60
Drill Drawing:
  circle w10: c4603.72,2027.28 r27.63
  lines w10: 4576.09,1516.19 4589.9,1516.19 4589.9,1502.38 4617.53,1502.38 4617.53,1516.19 4631.34,1516.19 4631.34,1543.82 4617.53,1543.82 4617.53,1557.63 4589.9,1557.63 4589.9,1543.82 4576.09,1543.82 4576.09,1516.19 ; 4576.09,1626.7 4603.72,1640.51 4631.34,1626.7 4617.53,1654.32 4631.34,1681.95 4603.72,1668.14 4576.09,1681.95 4589.9,1654.32 4576.09,1626.7 ; 4576.09,1751.02 4631.34,1751.02 4631.34,1806.27 4576.09,1806.27 4576.09,1751.02 ; 4576.09,1889.15 4589.9,1889.15 4603.72,1875.34 4617.53,1889.15 4631.34,1889.15 4617.53,1902.96 4631.34,1916.78 4617.53,1916.78 4603.72,1930.59 4589.9,1916.78 4576.09,1916.78 4589.9,1902.96 4576.09,1889.15
  lines w12: 4526,1465.08 7757.49,1465.08 ; 4526,2086.68 7757.49,2086.68 ; 4863.86,1340.76 4863.86,2211 ; 5195.86,1340.76 5195.86,2211 ; 5832.43,1340.76 5832.43,2211 ; 6091.57,1340.76 6091.57,2211 ; 6466.72,1340.76 6466.72,2211 ; 7191.05,1340.76 7191.05,2211 ; 4526,1340.76 7757.49,1340.76 7757.49,2211 4526,2211 4526,1340.76
  text "Symbol" at 4600.59,2123.98 h72
  text "Quantity" at 4901.16,2123.98 h72
  text "Finished Hole Size" at 5233.16,2123.98 h72
  text "Plated" at 5869.72,2123.98 h72
  text "Hole Type" at 6128.86,2123.98 h72
  text "Drill Layer Pair" at 6504.02,2123.98 h72
  text "Hole Tolerance" at 7228.35,2123.98 h72
  text "2" at 4901.16,1999.66 h60
  text "78.74mil (2.000mm)" at 5233.16,1999.66 h60
  text "NPTH" at 5869.72,1999.66 h60
  text "Round" at 6128.86,1999.66 h60
  text "Top Layer - Bottom Layer" at 6504.02,1999.66 h60
  text "3" at 4901.16,1875.34 h60
  text "7.87mil (0.200mm)" at 5233.16,1875.34 h60
  text "PTH" at 5869.72,1875.34 h60
  text "Round" at 6128.86,1875.34 h60
  text "Top Layer - Bottom Layer" at 6504.02,1875.34 h60
  text "76" at 4901.16,1751.02 h60
  text "10.00mil (0.254mm)" at 5233.16,1751.02 h60
  text "PTH" at 5869.72,1751.02 h60
  text "Round" at 6128.86,1751.02 h60
  text "Top Layer - Bottom Layer" at 6504.02,1751.02 h60
  text "10" at 4901.16,1626.7 h60
  text "40.00mil (1.016mm)" at 5233.16,1626.7 h60
  text "PTH" at 5869.72,1626.7 h60
  text "Round" at 6128.86,1626.7 h60
  text "Top Layer - Bottom Layer" at 6504.02,1626.7 h60
  text "14" at 4901.16,1502.38 h60
  text "62.99mil (1.600mm)" at 5233.16,1502.38 h60
  text "PTH" at 5869.72,1502.38 h60
  text "Round" at 6128.86,1502.38 h60
  text "Top Layer - Bottom Layer" at 6504.02,1502.38 h60
  text "105 Total" at 4901.16,1378.06 h60
  text ".Layer_Name" at 577,-858.49 h60
M17 Embedded Cavity:
  text ".Layer_Name" at 577,-858.49 h60
M18 Embedded Assembly:
  text ".Layer_Name" at 577,-858.49 h60
M19 Embedded Keepout:
  text ".Layer_Name" at 577,-858.49 h60

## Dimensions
0,-400 to 1000,-400 on M2 Board Dimensions
0,0 to 0,2204.72 on M2 Board Dimensions
0,0 to 3622.05,0 on M2 Board Dimensions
